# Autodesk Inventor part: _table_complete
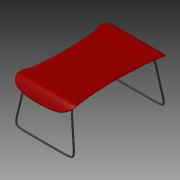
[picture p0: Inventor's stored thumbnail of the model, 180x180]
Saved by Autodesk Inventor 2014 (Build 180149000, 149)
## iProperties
Created: 2010-11
Part Number: _table_complete
Material: Generic
Document SubType Name: Modeling
Designer: PN
Density: 1 g/cm^3
Appearance: Default
Author: PN
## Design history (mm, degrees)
node "_table.wire1"
  feature "Base1"
  feature "Base2"
workplane "Work Plane1"
sketch "Sketch1"
  geometry: L1 (488.724, 890.588)-(395.196, 890.588); A1 r 181.229 centre (318.984, 954.088) between (465.59, 847.548) and (488.724, 890.588); A2 r 29.21 centre (441.96, 864.72) between (418.33, 847.548) and (465.59, 847.548); A3 r 181.229 centre (564.936, 954.088) between (395.196, 890.588) and (418.33, 847.548); 2 further points
  constraints: 6 point on circle, 3 centre point, 2 end point, 2 tangent, 1 equal radius, 1 horizontal, 1 midpoint, 1 vertical alignment
  dimensions: "d1" = 29.21 radius of A2; "d2" = 181.229 radius of A1; "d3" = 441.96 horizontal distance of point (441.96, 890.588) point (0, 0); "d19" = 890.5875 distance from line of point (0, 0) L1; "d20" = 63.5 distance from line of A3.centre L1; "d21" = 43.03925 distance from line of A1.start L1
sketch "Sketch2"
  geometry: 1 further point
extrude "Extrusion1" new body sketch "Sketch1" distance "d4" = 10.16; taper "d5" = 0 deg
sketch "Sketch3"
  geometry: L1 (-488.724, -890.588)-(-395.196, -890.588) reference; A1 r 181.229 centre (-318.984, -954.088) between (-465.59, -847.548) and (-488.724, -890.588) reference; A2 r 181.229 centre (-564.936, -954.088) between (-395.196, -890.588) and (-418.33, -847.548) reference; A3 r 29.21 centre (-441.96, -864.72) between (-418.33, -847.548) and (-465.59, -847.548) reference; A4 r 174.879 centre (-318.984, -954.088) between (-460.453, -851.281) and (-481.926, -890.588); A5 r 22.86 centre (-441.96, -864.72) between (-423.467, -851.281) and (-460.453, -851.281); A6 r 174.879 centre (-564.936, -954.088) between (-401.994, -890.588) and (-423.467, -851.281); 1 further point
  constraints: 6 point on circle, 3 centre point, 2 point on line, 2 tangent
  dimensions: "d6" = 6.35 radial gap between concentric circles of A4 A1
sketch "Sketch4"
  geometry: L1 (-488.724, 890.588)-(-395.196, 890.588) reference; A1 r 181.229 centre (-318.984, 954.088) between (-488.724, 890.588) and (-465.59, 847.548) reference; A2 r 29.21 centre (-441.96, 864.72) between (-465.59, 847.548) and (-418.33, 847.548) reference; A3 r 181.229 centre (-564.936, 954.088) between (-418.33, 847.548) and (-395.196, 890.588) reference; A4 r 174.879 centre (-564.936, 954.088) between (-423.467, 851.281) and (-401.994, 890.588); A5 r 22.86 centre (-441.96, 864.72) between (-460.453, 851.281) and (-423.467, 851.281); A6 r 174.879 centre (-318.984, 954.088) between (-481.926, 890.588) and (-460.453, 851.281); 1 further point
  constraints: 6 point on circle, 3 centre point, 2 point on line, 2 tangent
  dimensions: "d7" = 6.35 radial gap between concentric circles of A3 A4 (= d6)
extrude "Extrusion2" cut sketch "Sketch4" distance "d8" = 3.175; taper "d9" = 0 deg
extrude "Extrusion3" cut sketch "Sketch3" distance "d10" = 3.175; taper "d11" = 0.2 deg
fillet "Fillet4" dims "d22" = 5.08
fillet "Fillet5" dims "d23" = 1.27
sketch "Sketch6"
  geometry: C1 r 15.875 at (-441.96, -864.72); A1 r 21.597 centre (-441.96, -864.72) between (-424.489, -852.024) and (-459.431, -852.024) reference; 1 further point
  constraints: 1 centre point, 1 coincident
  dimensions: "d24" = 31.75 diameter of C1
extrude "Extrusion5" cut sketch "Sketch6" distance "d25" = 12.7; taper "d26" = 0 deg
pattern_linear "Rectangular Pattern1" dims "d29" = 33.02
mirror "Mirror1"
mirror "Mirror2"
combine "Combine2"
  body "Solid3"
fillet "Fillet7" dims "d31" = 1.27
node "TableTop"
node "Legs"
other parameters: "d0" = 546.1
